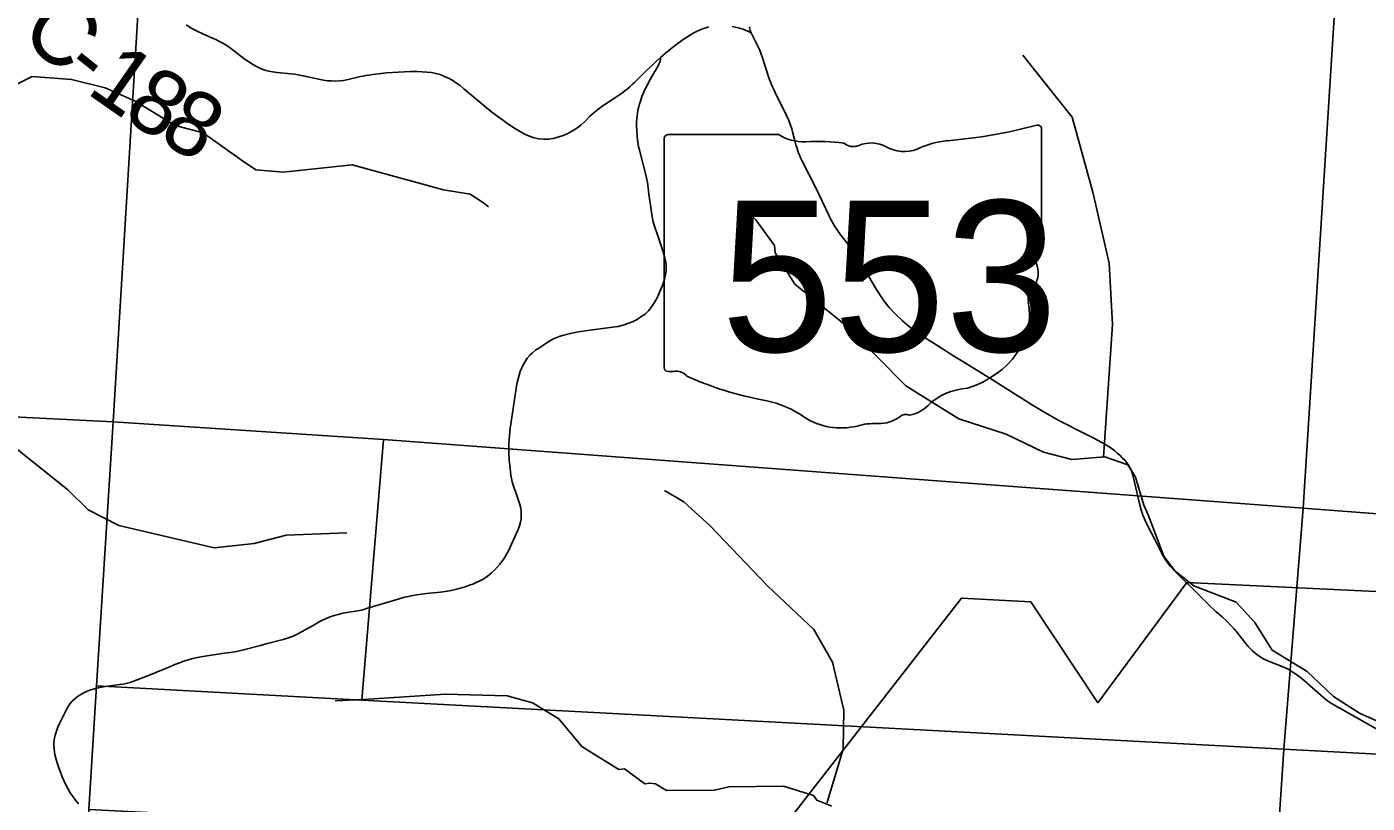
# Model space of a CAD drawing. Extents: x 0 to 34, y 0 to 22.
# Drawn here: x 25.938 to 27.11, y 15.067 to 15.745 of the extents above; entities that cross this region are included whole.
import ezdxf

# ---------------------------------------------------------------- set-up
doc = ezdxf.new("R2010")
doc.units = 0
for name, color, linetype in [('GM_X_Corporation', 7, 'Continuous'), ('GM_X_County_Road', 7, 'Continuous'), ('GM_X_County_Road_Text', 7, 'Continuous'), ('GM_X_Minor_River', 7, 'Continuous'), ('GM_X_Section', 7, 'Continuous'), ('GM_X_State_Location', 7, 'Continuous'), ('GM_X_State_Route', 7, 'Continuous'), ('GM_X_State_Shield', 7, 'Continuous'), ('GM_X_Township_Road', 7, 'Continuous')]:
    doc.layers.add(name, color=color, linetype=linetype)

msp = doc.modelspace()

# ---------------------------------------------------------------- linework, layer by layer
at = {"layer": 'GM_X_Corporation'}
msp.add_lwpolyline([(27.1862, 14.3829), (27.0716, 14.2873), (26.7502, 14.2997), (26.568, 14.3076), (26.1939, 14.3226), (26.1957, 14.4415), (26.1347, 14.9377), (26.5056, 14.9255), (26.755, 15.246), (26.8156, 15.2429), (26.8743, 15.1546), (26.9519, 15.2596), (27.2149, 15.247)], dxfattribs=at)
at = {"layer": 'GM_X_County_Road'}
for points in [[(26.0776, 15.7466), (26.0826, 15.7435), (26.0867, 15.7413), (26.0928, 15.7384), (26.0969, 15.7367), (26.1007, 15.735), (26.1035, 15.7337), (26.1063, 15.7324), (26.1091, 15.7309), (26.1117, 15.7294), (26.114, 15.7279), (26.1164, 15.7261), (26.1293, 15.7164), (26.1321, 15.7145), (26.1359, 15.712), (26.1398, 15.7098), (26.1433, 15.7082), (26.1473, 15.7068), (26.1514, 15.7058), (26.1569, 15.705), (26.1694, 15.7038), (26.1723, 15.7034), (26.1756, 15.7029), (26.1798, 15.702), (26.1948, 15.6988), (26.1977, 15.6983), (26.201, 15.6978), (26.2043, 15.6976), (26.2082, 15.6975), (26.2115, 15.6977), (26.2152, 15.6981), (26.2191, 15.6988), (26.23, 15.7015), (26.2323, 15.7019), (26.2347, 15.7024), (26.2373, 15.7028), (26.2406, 15.7033), (26.2527, 15.7046), (26.2578, 15.705), (26.263, 15.7054), (26.2685, 15.7057), (26.2734, 15.7058), (26.2791, 15.7058), (26.2837, 15.7057), (26.288, 15.7053), (26.2919, 15.7049), (26.2957, 15.7042), (26.2995, 15.7031), (26.3033, 15.7016), (26.3069, 15.7), (26.3107, 15.6979), (26.3139, 15.6958), (26.317, 15.6936), (26.3203, 15.6907), (26.3236, 15.6879), (26.3448, 15.6703), (26.3585, 15.6604), (26.364, 15.6567), (26.3689, 15.6537), (26.3729, 15.6514), (26.3766, 15.6496), (26.3809, 15.6481), (26.3855, 15.6471), (26.3901, 15.6467), (26.3945, 15.6468), (26.3983, 15.6474), (26.4024, 15.6485), (26.4069, 15.65), (26.411, 15.6518), (26.4153, 15.654), (26.4191, 15.6565), (26.4225, 15.6591), (26.4262, 15.6625), (26.4301, 15.6665), (26.4342, 15.6701), (26.4369, 15.6723), (26.4396, 15.6744), (26.442, 15.6761), (26.4448, 15.6779), (26.4584, 15.687), (26.4608, 15.6889), (26.4631, 15.6908), (26.4652, 15.6926), (26.4673, 15.6945), (26.4694, 15.6964), (26.4716, 15.6986), (26.4792, 15.7062), (26.492, 15.7181), (26.4982, 15.7233), (26.5025, 15.7269), (26.5074, 15.7306), (26.5128, 15.7344), (26.5173, 15.7374), (26.5211, 15.7395), (26.5236, 15.7407), (26.5261, 15.7419), (26.5288, 15.743), (26.5316, 15.744), (26.5344, 15.7449)], [(26.5547, 15.7452), (26.5576, 15.7446), (26.561, 15.7437), (26.5649, 15.7425), (26.5683, 15.7411), (26.5714, 15.7397)]]:
    msp.add_lwpolyline(points, dxfattribs=at)
at = {"layer": 'GM_X_Minor_River'}
for points in [[(25.7612, 15.722), (25.764, 15.7008), (25.7948, 15.6948), (25.8592, 15.6946), (25.907, 15.684), (25.9199, 15.6879), (25.9309, 15.6955), (25.943, 15.7016), (25.9775, 15.699), (26.0068, 15.6915), (26.033, 15.6801), (26.0679, 15.6586), (26.0926, 15.6522), (26.1268, 15.6279), (26.1385, 15.62), (26.1624, 15.6181), (26.2227, 15.6243), (26.3024, 15.6025), (26.3259, 15.5987), (26.3373, 15.5911), (26.3419, 15.5877)], [(26.8793, 15.3692), (26.8871, 15.4849), (26.8842, 15.5385), (26.8698, 15.6005), (26.8518, 15.666), (26.8292, 15.6944), (26.8088, 15.7201)], [(27.1334, 15.1319), (27.1028, 15.1454), (27.0802, 15.1601), (27.0571, 15.1818), (27.0266, 15.2006), (27.0115, 15.2246), (26.995, 15.2426), (26.958, 15.2567), (26.9414, 15.2697), (26.932, 15.2826), (26.9183, 15.3187), (26.9144, 15.3272), (26.9072, 15.3517), (26.9004, 15.3625), (26.8802, 15.3693), (26.8514, 15.3671), (26.8266, 15.3736), (26.7942, 15.3891), (26.7527, 15.4026), (26.7063, 15.4314), (26.6553, 15.4831), (26.6096, 15.5203), (26.5923, 15.5474), (26.5917, 15.5539), (26.5754, 15.5764), (26.5695, 15.5819), (26.5664, 15.5836)], [(25.7936, 15.4748), (25.8315, 15.4504), (25.8742, 15.4255), (25.8969, 15.4016), (25.9139, 15.3885), (25.9741, 15.3407), (25.9921, 15.323), (26.0189, 15.3093), (26.1022, 15.2899), (26.1371, 15.2938), (26.1649, 15.3009), (26.2179, 15.303)], [(26.6377, 15.0673), (26.6379, 15.0686), (26.6517, 15.1142), (26.6524, 15.1483), (26.6423, 15.19), (26.6262, 15.2186), (26.5857, 15.2567), (26.5359, 15.3088), (26.5124, 15.3301), (26.4957, 15.3401)], [(26.6418, 15.0644), (26.6286, 15.0697), (26.6259, 15.0735), (26.5995, 15.0818), (26.5518, 15.0813), (26.5394, 15.0782), (26.4974, 15.0781), (26.4876, 15.0838), (26.4827, 15.0845), (26.4785, 15.0838), (26.4607, 15.097), (26.4558, 15.0963), (26.4312, 15.1114), (26.4233, 15.1163), (26.4032, 15.1406), (26.3801, 15.1546), (26.3582, 15.1606), (26.3042, 15.162), (26.2327, 15.1576), (26.2078, 15.1564)]]:
    msp.add_lwpolyline(points, dxfattribs=at)
at = {"layer": 'GM_X_Section'}
msp.add_lwpolyline([(27.7971, 15.2681), (27.0537, 15.3245), (27.0819, 15.7717), (27.1082, 16.21), (27.1198, 16.4014)], dxfattribs=at)
for points in [[(26.0395, 15.8225), (26.0137, 15.3999), (24.9883, 15.4512), (25.0112, 15.8778)], [(27.0819, 15.7717), (27.0537, 15.3245), (26.2501, 15.3844), (26.0137, 15.3999), (26.0395, 15.8225)], [(24.9883, 15.4512), (26.0137, 15.3999), (25.9993, 15.1693), (25.9925, 15.0615), (25.9851, 14.9419), (25.9779, 14.8211), (25.9703, 14.6911), (25.9621, 14.5516), (25.9518, 14.384), (24.9287, 14.4241)], [(26.2501, 15.3844), (26.2311, 15.157), (25.9993, 15.1693), (26.0137, 15.3999)], [(27.0537, 15.3245), (27.0368, 15.114), (26.2311, 15.157), (26.2501, 15.3844)], [(27.0537, 15.3245), (27.7971, 15.2681), (27.7884, 15.2624), (27.7785, 15.2559), (27.771, 15.251), (27.7619, 15.2445), (27.743, 15.2331), (27.7146, 15.2152), (27.6987, 15.2038), (27.6828, 15.1924), (27.6624, 15.1753), (27.656, 15.1697), (27.6401, 15.159), (27.6276, 15.1491), (27.6174, 15.1393), (27.6042, 15.1237), (27.597, 15.1172), (27.5777, 15.1036), (27.5644, 15.0941), (27.5553, 15.0864), (27.0368, 15.114)], [(25.9993, 15.1693), (26.2311, 15.157), (27.0368, 15.114), (27.0298, 15.0085), (25.9925, 15.0615)], [(27.0368, 15.114), (27.5553, 15.0864), (27.5463, 15.0789), (27.5274, 15.0629), (27.4979, 15.0356), (27.4752, 15.0143), (27.4642, 15.0048), (27.447, 14.9872), (27.0298, 15.0085)]]:
    msp.add_lwpolyline(points, close=True, dxfattribs=at)
at = {"layer": 'GM_X_State_Route'}
for points in [[(26.9529, 15.2584), (26.9521, 15.2591), (26.9411, 15.2698), (26.9378, 15.2736), (26.9349, 15.2773), (26.9324, 15.281), (26.9303, 15.2844), (26.9239, 15.2971), (26.9176, 15.3093), (26.9155, 15.3137), (26.9136, 15.3185), (26.912, 15.3232), (26.9105, 15.3285), (26.9063, 15.3473), (26.9054, 15.3508), (26.9045, 15.3543), (26.9035, 15.3574), (26.9026, 15.3595), (26.9012, 15.3618), (26.8995, 15.3642), (26.8978, 15.3664), (26.8956, 15.3686), (26.8935, 15.3707), (26.8912, 15.3727), (26.8891, 15.3745), (26.8846, 15.3777), (26.8797, 15.3806), (26.8745, 15.3836), (26.8696, 15.3863), (26.8637, 15.3892), (26.8394, 15.4015), (26.8264, 15.4089), (26.8162, 15.4151), (26.7822, 15.4365), (26.7736, 15.4419), (26.7646, 15.4475), (26.7562, 15.4526), (26.749, 15.4571), (26.7343, 15.4662), (26.7233, 15.4734), (26.7159, 15.4783), (26.7096, 15.483), (26.7036, 15.488), (26.6974, 15.494), (26.692, 15.4999), (26.6876, 15.5054), (26.6839, 15.5105), (26.6793, 15.5179), (26.6697, 15.5343), (26.6675, 15.5383), (26.6655, 15.5415), (26.6634, 15.5446), (26.6612, 15.5479), (26.6584, 15.5518), (26.6489, 15.5642), (26.6469, 15.5668), (26.6449, 15.5696), (26.6433, 15.5725), (26.6413, 15.576), (26.6394, 15.5798), (26.6272, 15.6054), (26.6159, 15.6275), (26.6145, 15.6304), (26.6135, 15.6328), (26.6125, 15.6355), (26.6115, 15.6385), (26.6104, 15.6419), (26.6095, 15.6454), (26.6074, 15.6532), (26.6068, 15.6558), (26.6055, 15.66), (26.6042, 15.663), (26.6022, 15.6674), (26.5922, 15.6875), (26.591, 15.6902), (26.5896, 15.6932), (26.5884, 15.6961), (26.5871, 15.6995), (26.5828, 15.713), (26.5812, 15.7179), (26.5798, 15.7218), (26.5789, 15.7242), (26.578, 15.7262), (26.5771, 15.7281), (26.5714, 15.7397), (26.5709, 15.7406), (26.5705, 15.7418), (26.5701, 15.7429), (26.5698, 15.7439), (26.5697, 15.745)], [(27.1305, 15.1245), (27.0785, 15.1539), (27.0748, 15.1564), (27.0717, 15.1589), (27.0548, 15.1737), (27.0513, 15.1767), (27.0478, 15.1794), (27.0441, 15.1817), (27.0404, 15.1839), (27.0353, 15.1863), (27.0234, 15.1909), (27.019, 15.1929), (27.016, 15.1948), (27.013, 15.1968), (27.0094, 15.2), (27.0056, 15.2039), (26.9959, 15.216), (26.9934, 15.2191), (26.9905, 15.2222), (26.9868, 15.2259), (26.983, 15.2294), (26.9777, 15.2341), (26.9722, 15.2392), (26.9529, 15.2584)]]:
    msp.add_lwpolyline(points, dxfattribs=at)
at = {"layer": 'GM_X_State_Shield'}
for p, q in [((26.4954, 15.6473), (26.4954, 15.4472)), ((26.5952, 15.6508), (26.4986, 15.6508)), ((26.825, 15.5511), (26.825, 15.6557)), ((26.8249, 15.5511), (26.825, 15.5511))]:
    msp.add_line(p, q, dxfattribs=at)
for centre, major_axis, start_param, end_param in [((26.7076, 15.9236), (0.3495, 0), 4.814394, 5.042369), ((26.8213, 15.6562), (0.00367, 0), 6.141152, 7.989035), ((26.4992, 15.6478), (0.00382, 0), 1.712693, 3.28349), ((26.6181, 15.674), (0.037, 0), 4.042523, 4.731795), ((26.6304, 15.5384), (0.133, 0), 1.404758, 1.657858), ((26.6606, 15.6488), (0.0107, 0), 3.836095, 5.185415), ((26.6763, 15.6257), (0.0222, 0), 0.950623, 2.079405), ((26.705, 15.6574), (0.0267, 0), 4.081561, 5.145723), ((26.7522, 15.5897), (0.0703, 0), 1.699011, 2.107814), ((26.8241, 15.5434), (0.00568, 0), 1.883978, 3.671073), ((26.8211, 15.5507), (0.00393, 0), 5.05454, 6.418171), ((26.788, 15.5301), (0.0341, 0), 5.934695, 6.695948), ((26.8381, 15.5073), (0.0248, 0), 2.387724, 3.262537), ((26.7271, 15.4939), (0.0874, 0), 5.101752, 6.440018), ((26.4992, 15.4468), (0.00385, 0), 3.00124, 4.508301), ((26.4998, 15.4673), (0.0294, 0), 4.665946, 4.897461), ((26.5058, 15.4357), (0.0106, 0), 0.519207, 1.627899), ((26.6396, 15.6155), (0.2524, 0), 4.195997, 4.488961), ((26.764, 15.391), (0.0479, 0), 1.647645, 2.488434), ((26.5644, 15.3573), (0.079, 0), 0.823519, 1.323587), ((26.7033, 15.4278), (0.0282, 0), 4.937069, 5.64225), ((26.6498, 15.4347), (0.0501, 0), 4.026481, 4.996735), ((26.6824, 15.4197), (0.0267, 0), 4.691044, 5.507374), ((26.7066, 15.4003), (0.00752, 0), 1.147584, 2.315152), ((26.6787, 15.3655), (0.0412, 0), 1.495662, 1.94098)]:
    msp.add_ellipse(centre, major_axis=major_axis, ratio=0.8, start_param=start_param, end_param=end_param, dxfattribs=at)
at = {"layer": 'GM_X_Township_Road'}
msp.add_lwpolyline([(25.9835, 15.0664), (25.981, 15.0695), (25.9789, 15.0724), (25.9764, 15.0761), (25.9742, 15.0799), (25.9722, 15.0836), (25.9707, 15.0867), (25.9694, 15.0899), (25.9678, 15.094), (25.9665, 15.0977), (25.9653, 15.1013), (25.9641, 15.1051), (25.963, 15.1095), (25.9623, 15.114), (25.9621, 15.1185), (25.9624, 15.1226), (25.9631, 15.1263), (25.9642, 15.1297), (25.9656, 15.1332), (25.9673, 15.1372), (25.9728, 15.1482), (25.9742, 15.1508), (25.9761, 15.1536), (25.978, 15.1559), (25.9803, 15.1582), (25.9825, 15.1599), (25.9849, 15.1615), (25.9876, 15.163), (25.9906, 15.1645), (25.9935, 15.1655), (25.9963, 15.1665), (25.9997, 15.1674), (26.0035, 15.1682), (26.0072, 15.1689), (26.0114, 15.1694), (26.0157, 15.1699), (26.0194, 15.1705), (26.0227, 15.171), (26.026, 15.1716), (26.0288, 15.1724), (26.0311, 15.1732), (26.0446, 15.1783), (26.0639, 15.1863), (26.0678, 15.188), (26.0717, 15.1895), (26.0755, 15.1909), (26.0795, 15.1922), (26.0834, 15.1932), (26.0875, 15.1941), (26.0924, 15.1951), (26.0976, 15.1958), (26.1111, 15.1978), (26.1163, 15.1986), (26.1216, 15.1995), (26.1254, 15.2002), (26.129, 15.201), (26.1426, 15.2047), (26.1474, 15.206), (26.1623, 15.2099), (26.1671, 15.2114), (26.1711, 15.2129), (26.1758, 15.215), (26.1879, 15.2217), (26.191, 15.2236), (26.1937, 15.2252), (26.1968, 15.2268), (26.1999, 15.2282), (26.2034, 15.2296), (26.2069, 15.2308), (26.2105, 15.2318), (26.2144, 15.2328), (26.2181, 15.2334), (26.2218, 15.2339), (26.2257, 15.2345), (26.229, 15.2351), (26.2321, 15.2359), (26.2351, 15.2368), (26.2628, 15.2452), (26.2656, 15.246), (26.2685, 15.2467), (26.2719, 15.2475), (26.2756, 15.2482), (26.2793, 15.2488), (26.2832, 15.2494), (26.2875, 15.2499), (26.2999, 15.2513), (26.3039, 15.2519), (26.3079, 15.2524), (26.3116, 15.2532), (26.3151, 15.254), (26.3184, 15.255), (26.3223, 15.2562), (26.3252, 15.2572), (26.3281, 15.2582), (26.3311, 15.2595), (26.3342, 15.261), (26.337, 15.2625), (26.3397, 15.2643), (26.342, 15.266), (26.3445, 15.2681), (26.3469, 15.2704), (26.3494, 15.2731), (26.3517, 15.2757), (26.3537, 15.2783), (26.3558, 15.2813), (26.3576, 15.2843), (26.3589, 15.2868), (26.3678, 15.3059), (26.369, 15.309), (26.3698, 15.3123), (26.3703, 15.3153), (26.3704, 15.3183), (26.3703, 15.3216), (26.3699, 15.3246), (26.3691, 15.3279), (26.3681, 15.3312), (26.3653, 15.339), (26.3642, 15.3421), (26.3634, 15.3447), (26.3626, 15.3476), (26.362, 15.3504), (26.3614, 15.3534), (26.361, 15.3564), (26.3606, 15.3592), (26.3604, 15.3619), (26.3599, 15.3667), (26.3596, 15.3723), (26.3595, 15.3771), (26.3596, 15.3807), (26.3598, 15.3844), (26.3601, 15.3876), (26.3608, 15.3943), (26.3615, 15.4), (26.3663, 15.4312), (26.3669, 15.4343), (26.3676, 15.4376), (26.3685, 15.4408), (26.3696, 15.444), (26.3708, 15.4471), (26.372, 15.4498), (26.3737, 15.4527), (26.3756, 15.4556), (26.3778, 15.4582), (26.3801, 15.4602), (26.3828, 15.4624), (26.3857, 15.4644), (26.3936, 15.4694), (26.3961, 15.471), (26.3987, 15.4723), (26.4015, 15.4736), (26.4044, 15.4747), (26.4076, 15.4757), (26.411, 15.4765), (26.4146, 15.4773), (26.4186, 15.4781), (26.4224, 15.4788), (26.4263, 15.4794), (26.4501, 15.4825), (26.455, 15.4833), (26.4595, 15.4844), (26.4635, 15.4857), (26.4675, 15.4874), (26.4716, 15.4894), (26.475, 15.4915), (26.4788, 15.4941), (26.4815, 15.4968), (26.4846, 15.5008), (26.4871, 15.5047), (26.4897, 15.5095), (26.4916, 15.5138), (26.4937, 15.519), (26.4955, 15.5243), (26.4965, 15.5284), (26.497, 15.5318), (26.4971, 15.5349), (26.497, 15.5371), (26.4968, 15.5396), (26.4963, 15.5419), (26.4957, 15.5442), (26.4948, 15.5474), (26.4936, 15.5511), (26.4888, 15.5649), (26.4874, 15.5692), (26.4863, 15.5726), (26.4855, 15.5758), (26.4848, 15.5793), (26.4841, 15.5831), (26.4835, 15.5871), (26.4819, 15.5987), (26.4816, 15.6015), (26.4813, 15.6042), (26.481, 15.6067), (26.4806, 15.6092), (26.4802, 15.6116), (26.4796, 15.6146), (26.4743, 15.6347), (26.4737, 15.6374), (26.473, 15.6402), (26.4725, 15.6428), (26.472, 15.6458), (26.4716, 15.6496), (26.4713, 15.6539), (26.4711, 15.6588), (26.4711, 15.6616), (26.4713, 15.6645), (26.4716, 15.6672), (26.4719, 15.6694), (26.4724, 15.6721), (26.4731, 15.6749), (26.4738, 15.6777), (26.4749, 15.6809), (26.4759, 15.684), (26.4773, 15.6873), (26.4785, 15.6902), (26.48, 15.6932), (26.4822, 15.6973), (26.49, 15.7108), (26.491, 15.7128), (26.4917, 15.7147), (26.4921, 15.7165), (26.492, 15.7181)], dxfattribs=at)

# ---------------------------------------------------------------- texts
at = {"layer": 'GM_X_County_Road_Text'}
for s, rotation, p in [('C', 318.857, (25.9306, 15.7372)), ('-', 321.3811, (25.9678, 15.7047)), ('1', 325.1055, (25.9893, 15.6877)), ('8', 328.1275, (26.0207, 15.6659)), ('8', 329.4883, (26.0517, 15.6467))]:
    msp.add_text(s, height=0.0568, rotation=rotation, dxfattribs=at).set_placement(p)
at = {"layer": 'GM_X_State_Location'}
for s in ['s', 'r']:
    msp.add_text(s, height=0.000189, dxfattribs=at).set_placement((26.6565, 15.534))
msp.add_text('553', height=0.000189, rotation=0, dxfattribs=at).set_placement((26.5896, 15.5202))
at = {"layer": 'GM_X_State_Shield'}
msp.add_text('553', height=0.13184, dxfattribs=at).set_placement((26.5449, 15.4613))

doc.saveas('drawing.dxf')
